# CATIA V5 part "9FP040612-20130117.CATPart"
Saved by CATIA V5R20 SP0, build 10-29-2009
Part number: 9FP040612-20130117
Revision: ANY
Definition: UNKNOWN
Nomenclature: 9FP040612-20130117
Source: Unknown
Bounding box of the stored display mesh (mm): x -6 to 6, y -6 to 5.85, z 0 to 8
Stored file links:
  C:\Users\Utente\Desktop\IO LAVORO\3D X SITO CF\CUMSA\3D files PF\PF 0642WB\9FP040612-20130117.CATPart
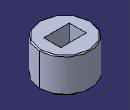
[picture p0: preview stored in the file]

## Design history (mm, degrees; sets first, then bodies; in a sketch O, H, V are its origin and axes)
Body1 "Chaflán1" (main body)
  Solid1: solid without history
